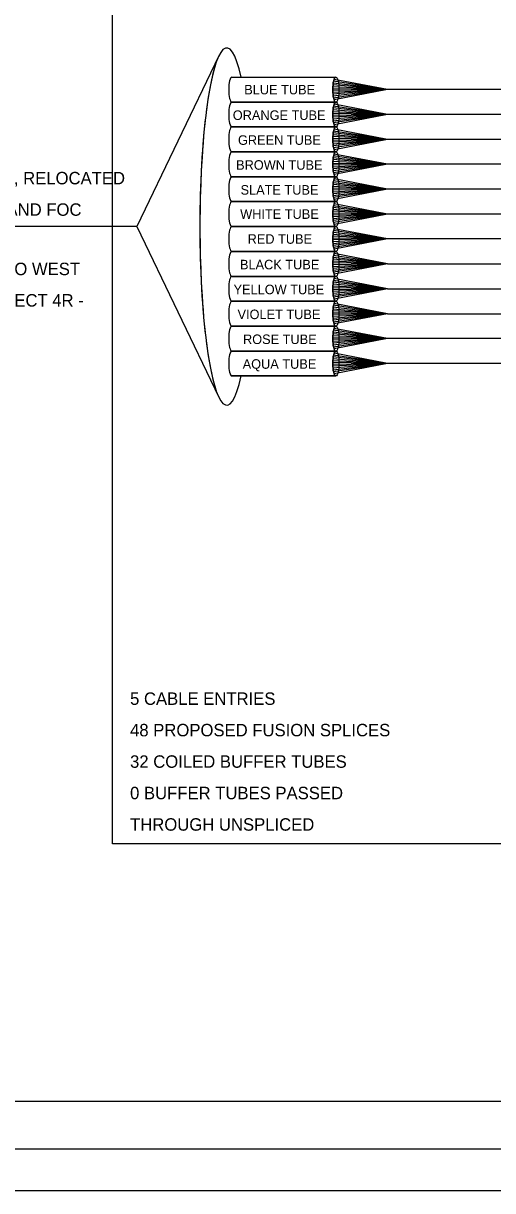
# Model space of a CAD drawing. Extents: x 1805893 to 1833564, y 708898 to 716199.
# Drawn here: x 1832336.4 to 1832449.4, y 713757.9 to 714039.2 of the extents above; entities that cross this region are included whole.
import ezdxf

# ---------------------------------------------------------------- set-up
doc = ezdxf.new("R2010")
doc.units = 0
for name, color, linetype in [('BR_P_Sub_Hidden', 7, 'Continuous'), ('SH_Border', 7, 'Continuous'), ('SH_Cut_Line', 7, 'Continuous'), ('SH_Data', 7, 'Continuous')]:
    doc.layers.add(name, color=color, linetype=linetype)

msp = doc.modelspace()

# ---------------------------------------------------------------- linework, layer by layer
at = {"layer": 'BR_P_Sub_Hidden'}
for points in [[(1832277.01, 714178.75), (1832747.57, 714178.75), (1832747.57, 713779.36), (1832277.01, 713779.36)], [(1832357.86, 714161.88), (1832653.35, 714161.88), (1832653.35, 713841.48), (1832357.86, 713841.48)]]:
    msp.add_lwpolyline(points, close=True, dxfattribs=at)
at = {"layer": 'SH_Border'}
msp.add_lwpolyline([(1832143.13, 714187.91), (1832773.13, 714187.91), (1832773.13, 713767.91), (1832143.13, 713767.91)], close=True, dxfattribs=at)
at = {"layer": 'SH_Cut_Line'}
msp.add_lwpolyline([(1832103.13, 713757.91), (1832783.13, 713757.91), (1832783.13, 714197.91), (1832103.13, 714197.91)], close=True, dxfattribs=at)
at = {"layer": 'SH_Data'}
for p, q in [((1832386.57, 714026.23), (1832411.63, 714026.23)), ((1832386.57, 714026.23), (1832411.63, 714026.23)), ((1832424.05, 714023.23), (1832410.93, 714024.35)), ((1832424.05, 714023.23), (1832410.99, 714024.8)), ((1832424.05, 714023.23), (1832411.07, 714025.25)), ((1832424.05, 714023.23), (1832411.2, 714025.7)), ((1832424.05, 714023.23), (1832410.88, 714023.45)), ((1832424.05, 714023.23), (1832410.88, 714023)), ((1832424.05, 714023.23), (1832410.89, 714023.9)), ((1832424.05, 714023.23), (1832410.89, 714022.55)), ((1832424.05, 714023.23), (1832410.93, 714022.1)), ((1832424.05, 714023.23), (1832410.99, 714021.65)), ((1832424.05, 714023.23), (1832411.07, 714021.2)), ((1832424.05, 714023.23), (1832411.2, 714020.75)), ((1832461.58, 714023.23), (1832424.05, 714023.23)), ((1832411.63, 714020.23), (1832386.57, 714020.23)), ((1832386.57, 714020.23), (1832411.63, 714020.23)), ((1832424.05, 714017.23), (1832410.99, 714018.8)), ((1832424.05, 714017.23), (1832411.07, 714019.25)), ((1832424.05, 714017.23), (1832411.2, 714019.7)), ((1832424.05, 714017.23), (1832410.88, 714017.45)), ((1832424.05, 714017.23), (1832410.88, 714017)), ((1832424.05, 714017.23), (1832410.89, 714017.9)), ((1832424.05, 714017.23), (1832410.89, 714016.55)), ((1832424.05, 714017.23), (1832410.93, 714018.35)), ((1832424.05, 714017.23), (1832410.93, 714016.1)), ((1832424.05, 714017.23), (1832410.99, 714015.65)), ((1832424.05, 714017.23), (1832411.07, 714015.2)), ((1832424.05, 714017.23), (1832411.2, 714014.75)), ((1832476.17, 714017.23), (1832424.05, 714017.23)), ((1832386.57, 714014.23), (1832411.63, 714014.23)), ((1832411.63, 714014.23), (1832386.57, 714014.23)), ((1832424.05, 714011.23), (1832411.07, 714013.25)), ((1832424.05, 714011.23), (1832411.2, 714013.7)), ((1832424.05, 714011.23), (1832410.88, 714011.45)), ((1832424.05, 714011.23), (1832410.88, 714011)), ((1832424.05, 714011.23), (1832410.89, 714011.9)), ((1832424.05, 714011.23), (1832410.89, 714010.55)), ((1832424.05, 714011.23), (1832410.93, 714012.35)), ((1832424.05, 714011.23), (1832410.93, 714010.1)), ((1832424.05, 714011.23), (1832410.99, 714012.8)), ((1832424.05, 714011.23), (1832410.99, 714009.65)), ((1832424.05, 714011.23), (1832411.07, 714009.2)), ((1832424.05, 714011.23), (1832411.2, 714008.75)), ((1832482.17, 714011.23), (1832424.05, 714011.23)), ((1832411.63, 714008.23), (1832386.57, 714008.23)), ((1832386.57, 714008.23), (1832411.63, 714008.23)), ((1832424.05, 714005.23), (1832411.2, 714007.7)), ((1832424.05, 714005.23), (1832410.88, 714005.45)), ((1832424.05, 714005.23), (1832410.88, 714005)), ((1832424.05, 714005.23), (1832410.89, 714005.9)), ((1832424.05, 714005.23), (1832410.89, 714004.55)), ((1832424.05, 714005.23), (1832410.93, 714006.35)), ((1832424.05, 714005.23), (1832410.93, 714004.1)), ((1832424.05, 714005.23), (1832410.99, 714006.8)), ((1832424.05, 714005.23), (1832410.99, 714003.65)), ((1832424.05, 714005.23), (1832411.07, 714007.25)), ((1832424.05, 714005.23), (1832411.07, 714003.2)), ((1832424.05, 714005.23), (1832411.2, 714002.75)), ((1832488.17, 714005.23), (1832424.05, 714005.23)), ((1832411.63, 714002.23), (1832386.57, 714002.23)), ((1832386.57, 714002.23), (1832411.63, 714002.23)), ((1832424.05, 713999.23), (1832410.88, 713999.45)), ((1832424.05, 713999.23), (1832410.88, 713999)), ((1832424.05, 713999.23), (1832410.89, 713999.9)), ((1832424.05, 713999.23), (1832410.89, 713998.55)), ((1832424.05, 713999.23), (1832410.93, 714000.35)), ((1832424.05, 713999.23), (1832410.93, 713998.1)), ((1832424.05, 713999.23), (1832410.99, 714000.8)), ((1832424.05, 713999.23), (1832410.99, 713997.65)), ((1832424.05, 713999.23), (1832411.07, 714001.25)), ((1832424.05, 713999.23), (1832411.07, 713997.2)), ((1832424.05, 713999.23), (1832411.2, 714001.7)), ((1832424.05, 713999.23), (1832411.2, 713996.75)), ((1832506.17, 713999.23), (1832424.05, 713999.23)), ((1832411.63, 713996.23), (1832386.57, 713996.23)), ((1832386.57, 713996.23), (1832411.63, 713996.23)), ((1832424.05, 713993.23), (1832410.88, 713993.45)), ((1832424.05, 713993.23), (1832410.89, 713993.9)), ((1832424.05, 713993.23), (1832410.93, 713994.35)), ((1832424.05, 713993.23), (1832410.99, 713994.8)), ((1832424.05, 713993.23), (1832411.07, 713995.25)), ((1832424.05, 713993.23), (1832411.2, 713995.7)), ((1832424.05, 713993.23), (1832410.88, 713993)), ((1832424.05, 713993.23), (1832410.89, 713992.55)), ((1832424.05, 713993.23), (1832410.93, 713992.1)), ((1832424.05, 713993.23), (1832410.99, 713991.65)), ((1832424.05, 713993.23), (1832411.07, 713991.2)), ((1832424.05, 713993.23), (1832411.2, 713990.75)), ((1832506.17, 713993.22), (1832424.05, 713993.19)), ((1832363.68, 713990.23), (1832311.2, 713990.23)), ((1832411.63, 713990.23), (1832386.57, 713990.23)), ((1832386.57, 713990.23), (1832411.63, 713990.23)), ((1832424.05, 713987.23), (1832410.89, 713987.9)), ((1832424.05, 713987.23), (1832410.93, 713988.35)), ((1832424.05, 713987.23), (1832410.99, 713988.8)), ((1832424.05, 713987.23), (1832411.07, 713989.25)), ((1832424.05, 713987.23), (1832411.2, 713989.7)), ((1832424.05, 713987.23), (1832410.88, 713987.45)), ((1832424.05, 713987.23), (1832410.88, 713987)), ((1832424.05, 713987.23), (1832410.89, 713986.55)), ((1832424.05, 713987.23), (1832410.93, 713986.1)), ((1832424.05, 713987.23), (1832410.99, 713985.65)), ((1832424.05, 713987.23), (1832411.07, 713985.2)), ((1832424.05, 713987.23), (1832411.2, 713984.75)), ((1832508.58, 713987.23), (1832424.05, 713987.23)), ((1832411.63, 713984.23), (1832386.57, 713984.23)), ((1832386.57, 713984.23), (1832411.63, 713984.23)), ((1832424.05, 713981.23), (1832410.93, 713982.35)), ((1832424.05, 713981.23), (1832410.99, 713982.8)), ((1832424.05, 713981.23), (1832411.07, 713983.25)), ((1832424.05, 713981.23), (1832411.2, 713983.7)), ((1832424.05, 713981.23), (1832410.88, 713981.45)), ((1832424.05, 713981.23), (1832410.88, 713981)), ((1832424.05, 713981.23), (1832410.89, 713981.9)), ((1832424.05, 713981.23), (1832410.89, 713980.55)), ((1832424.05, 713981.23), (1832410.93, 713980.1)), ((1832424.05, 713981.23), (1832410.99, 713979.65)), ((1832424.05, 713981.23), (1832411.07, 713979.2)), ((1832424.05, 713981.23), (1832411.2, 713978.75)), ((1832424.05, 713981.23), (1832514.58, 713981.23)), ((1832386.57, 713978.23), (1832411.63, 713978.23)), ((1832411.63, 713978.23), (1832386.57, 713978.23)), ((1832424.05, 713975.23), (1832410.99, 713976.8)), ((1832424.05, 713975.23), (1832411.07, 713977.25)), ((1832424.05, 713975.23), (1832411.2, 713977.7)), ((1832424.05, 713975.23), (1832410.88, 713975.45)), ((1832424.05, 713975.23), (1832410.88, 713975)), ((1832424.05, 713975.23), (1832410.89, 713975.9)), ((1832424.05, 713975.23), (1832410.89, 713974.55)), ((1832424.05, 713975.23), (1832410.93, 713976.35)), ((1832424.05, 713975.23), (1832410.93, 713974.1)), ((1832424.05, 713975.23), (1832410.99, 713973.65)), ((1832424.05, 713975.23), (1832411.07, 713973.2)), ((1832424.05, 713975.23), (1832411.2, 713972.75)), ((1832424.05, 713975.23), (1832520.58, 713975.23)), ((1832411.63, 713972.23), (1832386.57, 713972.23)), ((1832386.57, 713972.23), (1832411.63, 713972.23)), ((1832424.05, 713969.23), (1832411.07, 713971.25)), ((1832424.05, 713969.23), (1832411.2, 713971.7)), ((1832424.05, 713969.23), (1832410.88, 713969.45)), ((1832424.05, 713969.23), (1832410.88, 713969)), ((1832424.05, 713969.23), (1832410.89, 713969.9)), ((1832424.05, 713969.23), (1832410.89, 713968.55)), ((1832424.05, 713969.23), (1832410.93, 713970.35)), ((1832424.05, 713969.23), (1832410.93, 713968.1)), ((1832424.05, 713969.23), (1832410.99, 713970.8)), ((1832424.05, 713969.23), (1832410.99, 713967.65)), ((1832424.05, 713969.23), (1832411.07, 713967.2)), ((1832424.05, 713969.23), (1832411.2, 713966.75)), ((1832424.05, 713969.23), (1832526.58, 713969.23)), ((1832411.63, 713966.23), (1832386.57, 713966.23)), ((1832386.57, 713966.23), (1832411.63, 713966.23)), ((1832424.05, 713963.23), (1832411.2, 713965.7)), ((1832424.05, 713963.23), (1832410.88, 713963.45)), ((1832424.05, 713963.23), (1832410.88, 713963)), ((1832424.05, 713963.23), (1832410.89, 713963.9)), ((1832424.05, 713963.23), (1832410.89, 713962.55)), ((1832424.05, 713963.23), (1832410.93, 713964.35)), ((1832424.05, 713963.23), (1832410.93, 713962.1)), ((1832424.05, 713963.23), (1832410.99, 713964.8)), ((1832424.05, 713963.23), (1832410.99, 713961.65)), ((1832424.05, 713963.23), (1832411.07, 713965.25)), ((1832424.05, 713963.23), (1832411.07, 713961.2)), ((1832424.05, 713963.23), (1832411.2, 713960.75)), ((1832532.59, 713963.23), (1832424.05, 713963.23)), ((1832411.63, 713960.23), (1832386.57, 713960.23)), ((1832386.57, 713960.23), (1832411.63, 713960.23)), ((1832424.05, 713957.23), (1832411.2, 713959.7)), ((1832424.05, 713957.23), (1832410.88, 713957.45)), ((1832424.05, 713957.23), (1832410.88, 713957)), ((1832424.05, 713957.23), (1832410.89, 713957.9)), ((1832424.05, 713957.23), (1832410.89, 713956.55)), ((1832424.05, 713957.23), (1832410.93, 713958.35)), ((1832424.05, 713957.23), (1832410.93, 713956.1)), ((1832424.05, 713957.23), (1832410.99, 713958.8)), ((1832424.05, 713957.23), (1832410.99, 713955.65)), ((1832424.05, 713957.23), (1832411.07, 713959.25)), ((1832424.05, 713957.23), (1832411.07, 713955.2)), ((1832424.05, 713957.23), (1832411.2, 713954.75)), ((1832538.58, 713957.23), (1832424.05, 713957.19)), ((1832411.63, 713954.23), (1832386.57, 713954.23)), ((1832386.57, 713954.23), (1832411.63, 713954.23)), ((1832411.63, 713954.23), (1832388.86, 713954.23))]:
    msp.add_line(p, q, dxfattribs=at)
msp.add_lwpolyline([(1832383.41, 714031.33), (1832363.68, 713990.23), (1832383.41, 713949.13)], dxfattribs=at)
msp.add_lwpolyline([(1832383.41, 714031.33), (1832363.68, 713990.23), (1832383.41, 713949.13)], dxfattribs=at)
for centre, major_axis, ratio, start_param, end_param in [((1832385.33, 713990.23), (0, -43.05), 0.149566, 2.561295, 6.863483), ((1832385.33, 713990.23), (0, -43.05), 0.149566, 2.561295, 6.863483), ((1832385.33, 713990.23), (0, -43.05), 0.149566, 3.443628, 5.98115), ((1832386.57, 714023.23), (0, -3), 0.25, 3.141593, 6.283185), ((1832386.57, 714023.23), (0, -3), 0.25, 3.141593, 6.283185), ((1832411.63, 714023.23), (0, -3), 0.25, 3.141593, 6.283185), ((1832386.57, 714017.23), (0, -3), 0.25, 3.141593, 6.283185), ((1832386.57, 714017.23), (0, -3), 0.25, 3.141593, 6.283185), ((1832411.63, 714017.23), (0, -3), 0.25, 3.141593, 6.283185), ((1832386.57, 714011.23), (0, -3), 0.25, 3.141593, 6.283185), ((1832386.57, 714011.23), (0, -3), 0.25, 3.141593, 6.283185), ((1832411.63, 714011.23), (0, -3), 0.25, 3.141593, 6.283185), ((1832386.57, 714005.23), (0, -3), 0.25, 3.141593, 6.283185), ((1832386.57, 714005.23), (0, -3), 0.25, 3.141593, 6.283185), ((1832411.63, 714005.23), (0, -3), 0.25, 3.141593, 6.283185), ((1832386.57, 713999.23), (0, -3), 0.25, 3.141593, 6.283185), ((1832386.57, 713999.23), (0, -3), 0.25, 3.141593, 6.283185), ((1832411.63, 713999.23), (0, -3), 0.25, 3.141593, 6.283185), ((1832386.57, 713993.23), (0, -3), 0.25, 3.141593, 6.283185), ((1832386.57, 713993.23), (0, -3), 0.25, 3.141593, 6.283185), ((1832411.63, 713993.23), (0, -3), 0.25, 3.141593, 6.283185), ((1832386.57, 713987.23), (0, -3), 0.25, 3.141593, 6.283185), ((1832386.57, 713987.23), (0, -3), 0.25, 3.141593, 6.283185), ((1832411.63, 713987.23), (0, -3), 0.25, 3.141593, 6.283185), ((1832386.57, 713981.23), (0, -3), 0.25, 3.141593, 6.283185), ((1832386.57, 713981.23), (0, -3), 0.25, 3.141593, 6.283185), ((1832411.63, 713981.23), (0, -3), 0.25, 3.141593, 6.283185), ((1832386.57, 713975.23), (0, -3), 0.25, 3.141593, 6.283185), ((1832386.57, 713975.23), (0, -3), 0.25, 3.141593, 6.283185), ((1832411.63, 713975.23), (0, -3), 0.25, 3.141593, 6.283185), ((1832386.57, 713969.23), (0, -3), 0.25, 3.141593, 6.283185), ((1832386.57, 713969.23), (0, -3), 0.25, 3.141593, 6.283185), ((1832411.63, 713969.23), (0, -3), 0.25, 3.141593, 6.283185), ((1832386.57, 713963.23), (0, -3), 0.25, 3.141593, 6.283185), ((1832386.57, 713963.23), (0, -3), 0.25, 3.141593, 6.283185), ((1832411.63, 713963.23), (0, -3), 0.25, 3.141593, 6.283185), ((1832386.57, 713957.23), (0, -3), 0.25, 3.141593, 6.283185), ((1832386.57, 713957.23), (0, -3), 0.25, 3.141593, 6.283185), ((1832411.63, 713957.23), (0, -3), 0.25, 3.141593, 6.283185)]:
    msp.add_ellipse(centre, major_axis=major_axis, ratio=ratio, start_param=start_param, end_param=end_param, dxfattribs=at)
for centre in [(1832411.63, 714023.23), (1832411.63, 714017.23), (1832411.63, 714011.23), (1832411.63, 714005.23), (1832411.63, 713999.23), (1832411.63, 713993.23), (1832411.63, 713987.23), (1832411.63, 713981.23), (1832411.63, 713975.23), (1832411.63, 713969.23), (1832411.63, 713963.23), (1832411.63, 713957.23)]:
    msp.add_ellipse(centre, major_axis=(0, -3), ratio=0.25, dxfattribs=at)

# ---------------------------------------------------------------- texts
for s, height, p in [('BLUE TUBE', 2.295, (1832389.57, 714022.08)), ('ORANGE TUBE', 2.2947, (1832386.81, 714015.92)), ('GREEN TUBE', 2.295, (1832388.06, 714009.92)), ('BROWN TUBE', 2.295, (1832387.61, 714003.92)), ('EXISTNG, RELOCATED', 3, (1832316.5, 714000.4)), ('SLATE TUBE', 2.295, (1832388.68, 713997.92)), ('144 STRAND FOC', 3, (1832316.5, 713992.82)), ('WHITE TUBE', 2.295, (1832388.59, 713992.08)), ('RED TUBE', 2.295, (1832390.38, 713986.08)), ('BLACK TUBE', 2.295, (1832388.54, 713979.92)), ('EXISTING, RELOCATED TO WEST', 3, (1832285.18, 713978.52)), ('(CONSTRUCTED IN PROJECT 4R - ', 3, (1832285.18, 713970.95)), ('YELLOW TUBE', 2.2947, (1832387, 713973.92)), ('VIOLET TUBE', 2.2947, (1832387.95, 713967.92)), ('ROSE TUBE', 2.295, (1832389.27, 713961.92)), ('AQUA TUBE', 2.295, (1832389.19, 713955.96)), ('5 CABLE ENTRIES', 3, (1832362.08, 713874.97)), ('48 PROPOSED FUSION SPLICES', 3, (1832362.08, 713867.39)), ('32 COILED BUFFER TUBES', 3, (1832362.08, 713859.81)), ('0 BUFFER TUBES PASSED ', 3, (1832362.08, 713852.23)), ('THROUGH UNSPLICED', 3, (1832362.08, 713844.65))]:
    msp.add_text(s, height=height, dxfattribs=at).set_placement(p)

doc.saveas('drawing.dxf')
